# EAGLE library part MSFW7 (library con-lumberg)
MSF CONNECTOR
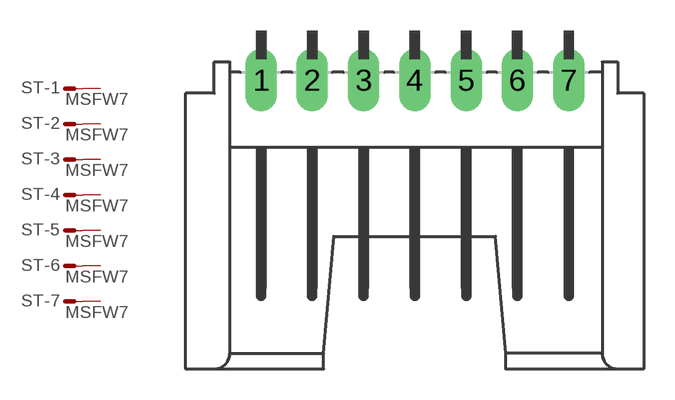
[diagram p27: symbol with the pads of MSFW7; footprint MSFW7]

Designator prefix ST; gates -1=M -2=M -3=M -4=M -5=M -6=M -7=M

## MSFW7 (OC_FARNELL: unknown; OC_NEWARK: unknown)  [MSFW7]
1  -1:S  pas
2  -2:S  pas
3  -3:S  pas
4  -4:S  pas
5  -5:S  pas
6  -6:S  pas
7  -7:S  pas

## Footprint MSFW7 (pad centres in mm)
MSF CONNECTOR
drill 1.016 long: 1 0,1.905; 2 2.489,1.905; 3 5.004,1.905; 4 7.493,1.905; 5 10.008,1.905; 6 12.497,1.905; 7 15.011,1.905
